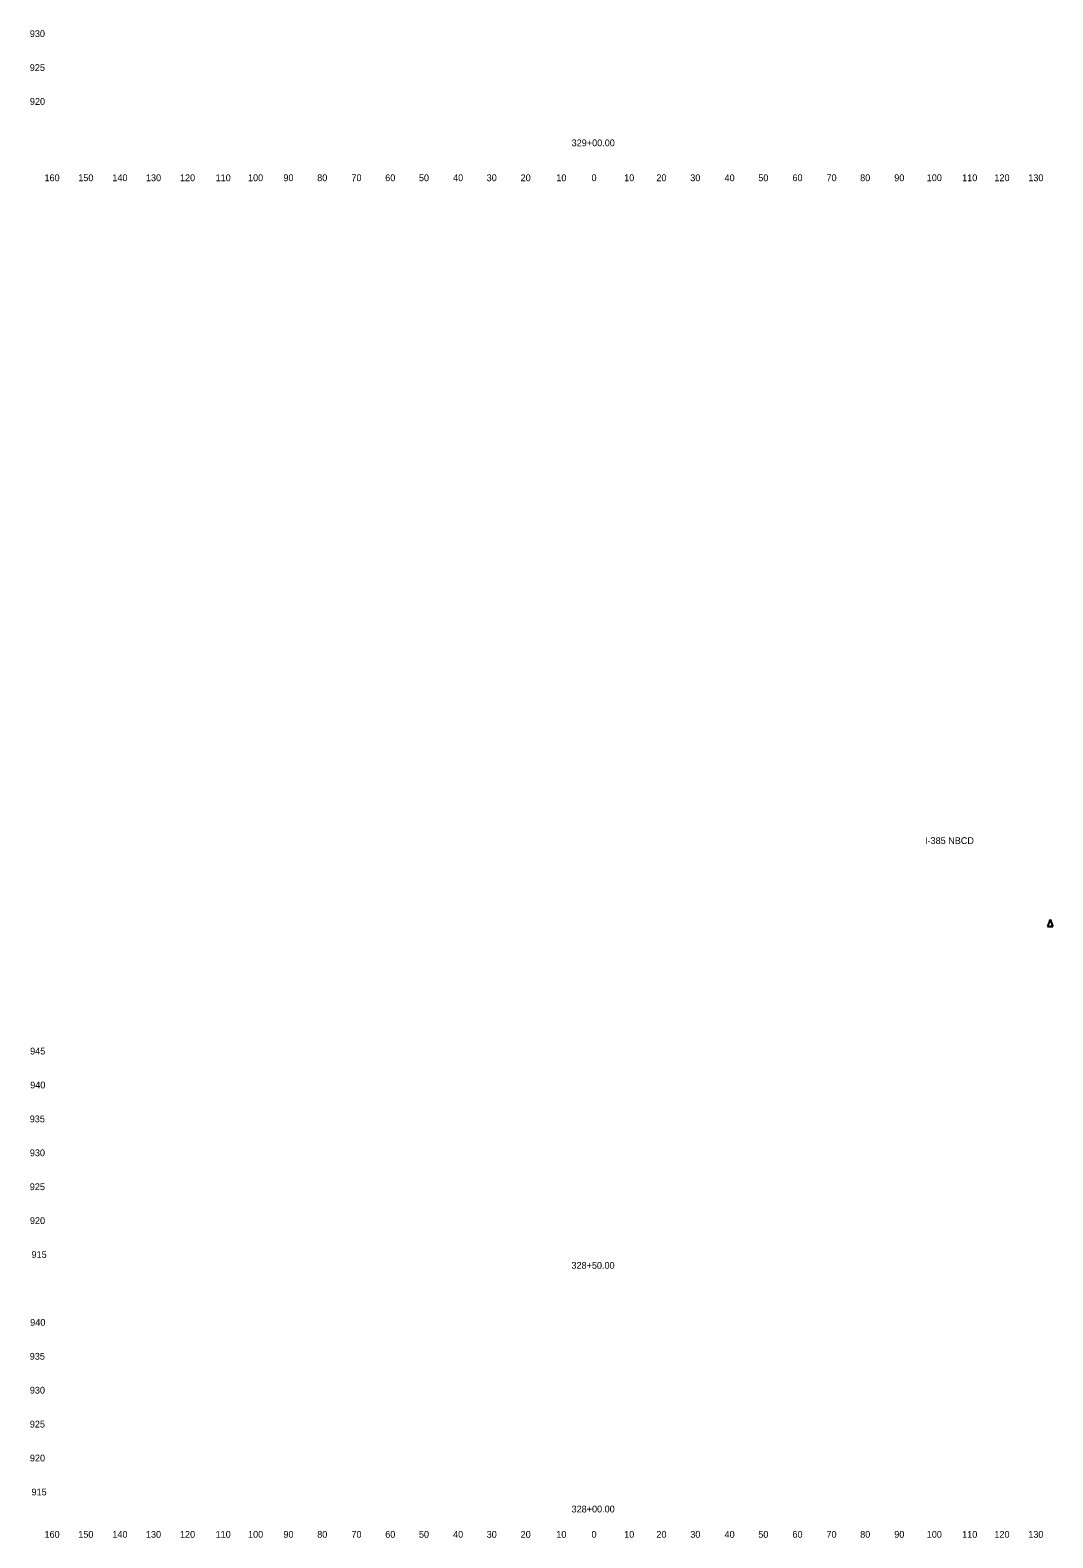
# Model space of a CAD drawing. Extents: x 4994 to 7391, y 4997 to 8804.
# Drawn here: x 4993.9 to 5295.2, y 4997.5 to 5442 of the extents above; entities that cross this region are included whole.
import ezdxf

# ---------------------------------------------------------------- set-up
doc = ezdxf.new("R2010")
doc.units = 0
for name, color, linetype in [('RD_SHT_ID', 7, 'Continuous'), ('RD_SHT_TX', 7, 'Continuous'), ('RD_XS_TX_Offset', 7, 'Continuous'), ('RD_XS_TX_Station', 7, 'Continuous')]:
    doc.layers.add(name, color=color, linetype=linetype)

msp = doc.modelspace()

# ---------------------------------------------------------------- linework, layer by layer
at = {"layer": 'RD_SHT_TX'}
for p, q in [((5294.43, 5179.78), (5293.63, 5177.75)), ((5294.43, 5179.78), (5295.23, 5177.75)), ((5293.63, 5177.75), (5295.23, 5177.75))]:
    msp.add_line(p, q, dxfattribs=at)

# ---------------------------------------------------------------- texts
at = {"layer": 'RD_SHT_ID'}
msp.add_text('I-385 NBCD', height=2, dxfattribs=at).set_placement((5257.56, 5202.06))
at = {"layer": 'RD_SHT_TX'}
msp.add_text('1', height=0.88, dxfattribs=at).set_placement((5294.43, 5178.08))
at = {"layer": 'RD_XS_TX_Offset'}
for s, p in [('930', (4993.78, 5440)), ('925', (4993.77, 5430)), ('920', (4993.8, 5420)), ('160', (4998.1, 5397.5)), ('150', (5008.04, 5397.5)), ('140', (5018.1, 5397.5)), ('130', (5027.99, 5397.5)), ('120', (5038.01, 5397.5)), ('110', (5048.51, 5397.5)), ('100', (5058.07, 5397.5)), ('90', (5068.5, 5397.5)), ('80', (5078.46, 5397.5)), ('70', (5088.54, 5397.5)), ('60', (5098.5, 5397.5)), ('50', (5108.43, 5397.5)), ('40', (5118.5, 5397.5)), ('30', (5128.39, 5397.5)), ('20', (5138.4, 5397.5)), ('10', (5148.91, 5397.5)), ('0', (5159.3, 5397.5)), ('0', (5159.3, 5397.5)), ('10', (5168.91, 5397.5)), ('20', (5178.4, 5397.5)), ('30', (5188.39, 5397.5)), ('40', (5198.5, 5397.5)), ('50', (5208.43, 5397.5)), ('60', (5218.5, 5397.5)), ('70', (5228.54, 5397.5)), ('80', (5238.46, 5397.5)), ('90', (5248.5, 5397.5)), ('100', (5258.07, 5397.5)), ('110', (5268.51, 5397.5)), ('120', (5278.01, 5397.5)), ('130', (5287.99, 5397.5)), ('945', (4993.86, 5140)), ('940', (4993.89, 5130)), ('935', (4993.75, 5120)), ('930', (4993.78, 5110)), ('925', (4993.77, 5100)), ('920', (4993.8, 5090)), ('915', (4994.27, 5080)), ('940', (4993.89, 5060)), ('935', (4993.75, 5050)), ('930', (4993.78, 5040)), ('925', (4993.77, 5030)), ('920', (4993.8, 5020)), ('915', (4994.27, 5010)), ('160', (4998.1, 4997.5)), ('150', (5008.04, 4997.5)), ('140', (5018.1, 4997.5)), ('130', (5027.99, 4997.5)), ('120', (5038.01, 4997.5)), ('110', (5048.51, 4997.5)), ('100', (5058.07, 4997.5)), ('90', (5068.5, 4997.5)), ('80', (5078.46, 4997.5)), ('70', (5088.54, 4997.5)), ('60', (5098.5, 4997.5)), ('50', (5108.43, 4997.5)), ('40', (5118.5, 4997.5)), ('30', (5128.39, 4997.5)), ('20', (5138.4, 4997.5)), ('10', (5148.91, 4997.5)), ('0', (5159.3, 4997.5)), ('0', (5159.3, 4997.5)), ('10', (5168.91, 4997.5)), ('20', (5178.4, 4997.5)), ('30', (5188.39, 4997.5)), ('40', (5198.5, 4997.5)), ('50', (5208.43, 4997.5)), ('60', (5218.5, 4997.5)), ('70', (5228.54, 4997.5)), ('80', (5238.46, 4997.5)), ('90', (5248.5, 4997.5)), ('100', (5258.07, 4997.5)), ('110', (5268.51, 4997.5)), ('120', (5278.01, 4997.5)), ('130', (5287.99, 4997.5))]:
    msp.add_text(s, height=2, dxfattribs=at).set_placement(p)
at = {"layer": 'RD_XS_TX_Station'}
for s, p in [('329+00.00', (5153.44, 5407.8)), ('328+50.00', (5153.38, 5076.82)), ('328+00.00', (5153.41, 5004.96))]:
    msp.add_text(s, height=2, dxfattribs=at).set_placement(p)

doc.saveas('drawing.dxf')
